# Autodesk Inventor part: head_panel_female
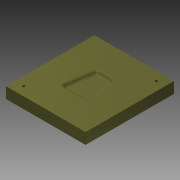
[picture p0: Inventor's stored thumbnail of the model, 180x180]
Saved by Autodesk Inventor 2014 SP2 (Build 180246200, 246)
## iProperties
Created: 2015-02
Part Number: head_panel_female
Material: Generic
Document SubType Name: Modeling
Designer: s41632
Density: 1 g/cm^3
Appearance: Titanium
Author: s41632
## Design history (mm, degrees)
sketch "Sketch9"
  geometry: L1 (0, 0)-(180, 0); L2 (180, 0)-(180, 200); L3 (180, 200)-(0, 200); L4 (0, 200)-(0, 0)
  constraints: 8 end point, 2 parallel, 1 horizontal, 1 perpendicular
  dimensions: "d73" = 200 distance of L3.end L1.start; "d74" = 180 distance between parallel lines of L4 L2
extrude "Extrusion7" new body sketch "Sketch9" distance "d75" = 25; taper "d76" = 0 deg
sketch "Sketch11"
  geometry: L1 (180, 0)-(180, 200) reference; L2 (180, 200)-(0, 200) reference; L3 (0, 200)-(0, 0) reference; L4 (62, 67)-(118, 67); L5 (118, 67)-(108, 133); L6 (108, 133)-(72, 133); L7 (72, 133)-(62, 67); 6 further points
  constraints: 8 end point, 6 midpoint, 2 horizontal alignment, 2 vertical alignment, 1 parallel, 1 perpendicular
  dimensions: "d80" = 36 distance of L5.end L6.end; "d81" = 56 distance of L4.start L4.end; "d82" = 66 distance between parallel lines of L6 L4
extrude "Extrusion8" cut sketch "Sketch11" distance "d83" = 6; taper "d84" = 0 deg
fillet "Fillet6" dims "d88" = 5
fillet "Fillet7" dims "d89" = 6
fillet "Fillet8" dims "d90" = 6
sketch "Sketch12"
  geometry: L1 (0, 0)-(180, 0) reference; L2 (180, 0)-(180, 200) reference; L3 (180, 200)-(0, 200) reference; L4 (0, 200)-(0, 0) reference; C1 r 3 at (20, 20); C2 r 3 at (160, 180)
  constraints: 2 centre point, 1 equal radius
  dimensions: "d91" = 6 diameter of C1; "d92" = 20 distance from line of L1 C1.centre; "d93" = 20 distance from line of L4 C1.centre; "d94" = 20 distance from line of L2 C2.centre; "d95" = 20 distance from line of L3 C2.centre
extrude "Extrusion9" cut sketch "Sketch12" distance "d96" = 15; taper "d97" = 0 deg
body "Solid2"
